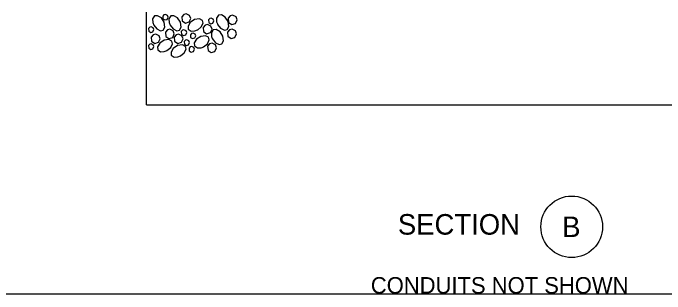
# Model space of a CAD drawing. Extents: x 99862 to 112891, y 95370 to 105076.
# Drawn here: x 101454 to 102089, y 100000 to 100273 of the extents above; entities that cross this region are included whole.
import ezdxf

# ---------------------------------------------------------------- set-up
doc = ezdxf.new("R2010")
doc.units = 0
for name, color, linetype in [('Level 1', 7, 'Continuous'), ('Level 12', 7, 'Continuous'), ('Level 15', 7, 'Continuous'), ('Level 20', 7, 'Continuous'), ('Level 5', 7, 'Continuous')]:
    doc.layers.add(name, color=color, linetype=linetype)

msp = doc.modelspace()

# ---------------------------------------------------------------- linework, layer by layer
at = {"layer": 'Level 1'}
msp.add_lwpolyline([(99862, 99999.5), (103151, 99999.5), (103151, 102075.5), (99862, 102075.5)], close=True, dxfattribs=at)
at = {"layer": 'Level 12'}
for points in [[(101591.13, 100261.35), (101594.08, 100257.62), (101597.78, 100255.89), (101600.37, 100256.52), (101601.96, 100259.4), (101601.3, 100264.11), (101598.51, 100268.34), (101594.85, 100270.53), (101591.92, 100270.26), (101590.02, 100267.43), (101590.19, 100263.82), (101591.23, 100261.16)], [(101599.81, 100270.02), (101600.03, 100267.56), (101601.93, 100266.32), (101604.11, 100266.94), (101605.05, 100269.04), (101604.42, 100270.74), (101602.41, 100271.72), (101600.98, 100271.36), (101599.81, 100270.02)], [(101606.96, 100261.33), (101609.91, 100257.6), (101613.61, 100255.88), (101616.2, 100256.5), (101617.79, 100259.38), (101617.13, 100264.09), (101614.34, 100268.32), (101610.68, 100270.51), (101607.75, 100270.24), (101605.85, 100267.41), (101606.02, 100263.8), (101607.06, 100261.14)], [(101618.39, 100269.55), (101618.76, 100265.46), (101621.92, 100263.38), (101625.55, 100264.43), (101627.13, 100267.92), (101626.08, 100270.76), (101622.72, 100272.39), (101620.35, 100271.79), (101618.39, 100269.55)], [(101653.26, 100262.02), (101656.21, 100258.29), (101659.91, 100256.56), (101662.5, 100257.19), (101664.09, 100260.07), (101663.43, 100264.78), (101660.64, 100269.01), (101656.98, 100271.2), (101654.05, 100270.93), (101652.15, 100268.1), (101652.32, 100264.49), (101653.36, 100261.83)], [(101663.6, 100268.09), (101663.97, 100264), (101667.13, 100261.93), (101670.76, 100262.97), (101672.34, 100266.46), (101671.29, 100269.3), (101667.92, 100270.93), (101665.56, 100270.34), (101663.6, 100268.09)], [(101633.67, 100256.57), (101637.4, 100259.52), (101639.12, 100263.22), (101638.5, 100265.81), (101635.61, 100267.4), (101630.91, 100266.73), (101626.68, 100263.94), (101624.48, 100260.29), (101624.76, 100257.35), (101627.59, 100255.46), (101631.2, 100255.62), (101633.86, 100256.67)], [(101639.1, 100259.16), (101639.46, 100255.07), (101642.62, 100253), (101646.25, 100254.04), (101647.83, 100257.53), (101646.78, 100260.37), (101643.42, 100262), (101641.05, 100261.41), (101639.1, 100259.16)], [(101644.5, 100266.36), (101644.72, 100263.9), (101646.61, 100262.66), (101648.79, 100263.29), (101649.74, 100265.38), (101649.11, 100267.09), (101647.09, 100268.07), (101645.67, 100267.71), (101644.5, 100266.36)], [(101586.02, 100257.92), (101586.24, 100255.46), (101588.13, 100254.21), (101590.31, 100254.84), (101591.26, 100256.94), (101590.63, 100258.64), (101588.61, 100259.62), (101587.19, 100259.26), (101586.02, 100257.91)], [(101602.4, 100254.49), (101602.76, 100250.4), (101605.92, 100248.32), (101609.55, 100249.37), (101611.13, 100252.86), (101610.08, 100255.7), (101606.72, 100257.33), (101604.35, 100256.74), (101602.4, 100254.49)], [(101617.93, 100255.08), (101618.15, 100252.62), (101620.05, 100251.38), (101622.23, 100252), (101623.17, 100254.1), (101622.54, 100255.8), (101620.52, 100256.78), (101619.1, 100256.42), (101617.93, 100255.08)], [(101648.31, 100247.86), (101651.26, 100244.13), (101654.95, 100242.4), (101657.54, 100243.03), (101659.14, 100245.91), (101658.47, 100250.62), (101655.68, 100254.84), (101652.03, 100257.04), (101649.09, 100256.77), (101647.2, 100253.94), (101647.36, 100250.33), (101648.41, 100247.67)], [(101663.01, 100254.53), (101663.37, 100250.44), (101666.53, 100248.36), (101670.16, 100249.41), (101671.74, 100252.9), (101670.69, 100255.74), (101667.33, 100257.37), (101664.96, 100256.78), (101663.01, 100254.53)], [(101588.72, 100249.73), (101589.09, 100245.63), (101592.25, 100243.56), (101595.88, 100244.6), (101597.46, 100248.09), (101596.41, 100250.94), (101593.05, 100252.57), (101590.68, 100251.97), (101588.73, 100249.73)], [(101610.89, 100249.75), (101611.25, 100245.66), (101614.41, 100243.59), (101618.05, 100244.63), (101619.62, 100248.12), (101618.57, 100250.97), (101615.21, 100252.59), (101612.84, 100252), (101610.89, 100249.75)], [(101626.82, 100251.86), (101627.04, 100249.41), (101628.94, 100248.16), (101631.12, 100248.79), (101632.07, 100250.88), (101631.44, 100252.59), (101629.42, 100253.57), (101628, 100253.21), (101626.83, 100251.86)], [(101639.67, 100240.22), (101643.4, 100243.18), (101645.13, 100246.87), (101644.51, 100249.46), (101641.62, 100251.05), (101636.91, 100250.39), (101632.69, 100247.6), (101630.49, 100243.94), (101630.77, 100241.01), (101633.6, 100239.11), (101637.2, 100239.28), (101639.86, 100240.32)], [(101586.02, 100241.44), (101586.24, 100238.98), (101588.13, 100237.74), (101590.31, 100238.37), (101591.26, 100240.46), (101590.63, 100242.17), (101588.61, 100243.14), (101587.19, 100242.79), (101586.02, 100241.44)], [(101603.89, 100236.45), (101607.62, 100239.4), (101609.35, 100243.09), (101608.72, 100245.68), (101605.84, 100247.28), (101601.13, 100246.61), (101596.91, 100243.82), (101594.71, 100240.17), (101594.98, 100237.23), (101597.81, 100235.34), (101601.42, 100235.5), (101604.08, 100236.55)], [(101620.72, 100245.27), (101620.94, 100242.82), (101622.84, 100241.57), (101625.02, 100242.2), (101625.96, 100244.3), (101625.33, 100246), (101623.31, 100246.98), (101621.89, 100246.62), (101620.72, 100245.28)], [(101643.56, 100240.78), (101643.93, 100236.68), (101647.09, 100234.61), (101650.72, 100235.65), (101652.3, 100239.14), (101651.25, 100241.99), (101647.89, 100243.62), (101645.52, 100243.02), (101643.57, 100240.78)], [(101617.1, 100231.3), (101620.83, 100234.25), (101622.56, 100237.95), (101621.93, 100240.53), (101619.05, 100242.13), (101614.34, 100241.46), (101610.11, 100238.67), (101607.92, 100235.02), (101608.19, 100232.08), (101611.02, 100230.19), (101614.63, 100230.35), (101617.29, 100231.4)], [(101625.49, 100238.85), (101625.71, 100236.39), (101627.61, 100235.15), (101629.79, 100235.77), (101630.74, 100237.87), (101630.11, 100239.57), (101628.09, 100240.55), (101626.67, 100240.19), (101625.5, 100238.85)]]:
    msp.add_lwpolyline(points, dxfattribs=at)
at = {"layer": 'Level 15'}
msp.add_circle((101997.94, 100064.91), 30, dxfattribs=at)
at = {"layer": 'Level 5'}
for q in [(101584.02, 100273.81), (102274.02, 100183.81)]:
    msp.add_line((101584.02, 100183.81), q, dxfattribs=at)

# ---------------------------------------------------------------- texts
at = {"layer": 'Level 20'}
for s, height, p in [('SECTION', 20, (101828.75, 100057.29)), ('B', 20, (101988.69, 100054.91)), ('CONDUITS NOT SHOWN', 16, (101802.43, 99999.94))]:
    msp.add_text(s, height=height, dxfattribs=at).set_placement(p)

doc.saveas('drawing.dxf')
